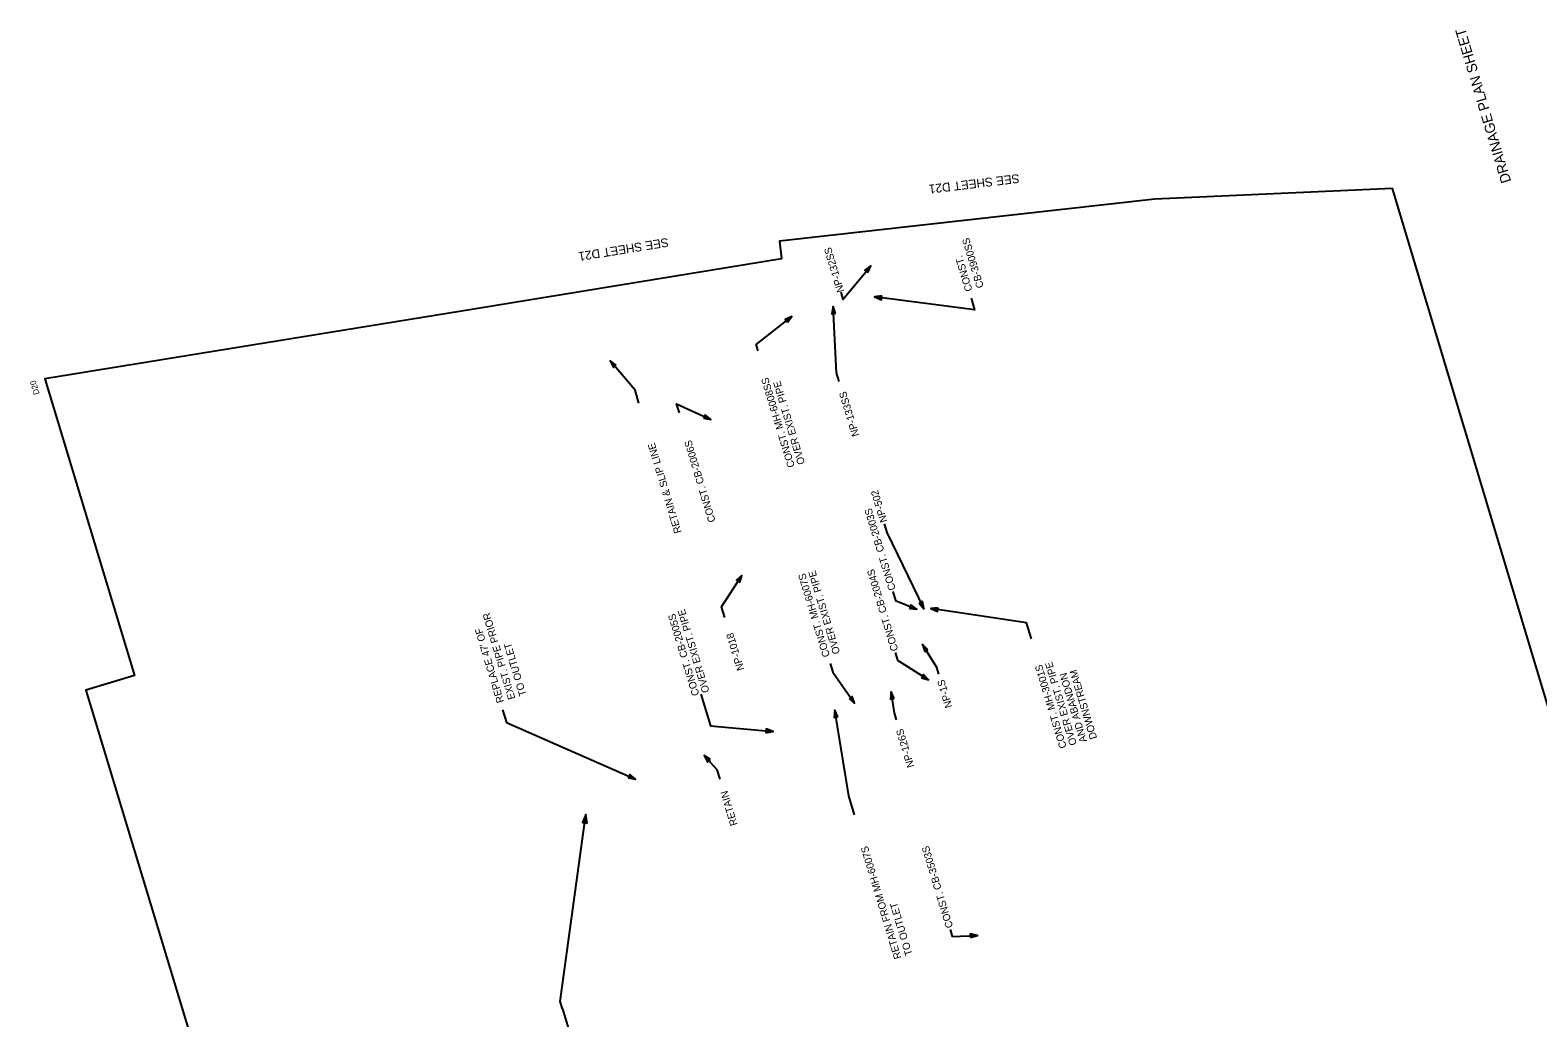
# Model space of a CAD drawing. Extents: x 1612099 to 1613927, y 1087002 to 1088782.
# Drawn here: x 1612099 to 1613125, y 1088109 to 1088782 of the extents above; entities that cross this region are included whole.
import ezdxf

# ---------------------------------------------------------------- set-up
doc = ezdxf.new("R2010")
doc.units = 0
for name, color, linetype in [('BR_CONCRETE', 7, 'Continuous'), ('RD_EX_Road', 7, 'Continuous'), ('RD_HC_CL', 7, 'Continuous'), ('RD_HY_Area_XP-Post sub TXT', 7, 'Continuous'), ('RD_HY_Misc', 7, 'Continuous')]:
    doc.layers.add(name, color=color, linetype=linetype)

msp = doc.modelspace()

# ---------------------------------------------------------------- linework, layer by layer
at = {"layer": 'BR_CONCRETE'}
msp.add_line((1612461.5, 1088115.6), (1612522, 1087914.2), dxfattribs=at)
for points in [[(1612650.9, 1088603.3), (1612652.4, 1088598.3), (1612671.3, 1088621.2)], [(1612649.9, 1088542.4), (1612648.1, 1088548.3), (1612645.7, 1088593.5)], [(1612739.6, 1088599.1), (1612742, 1088591.2), (1612673.9, 1088600)], [(1612594.6, 1088563.4), (1612593.3, 1088567.6), (1612617.7, 1088586.8)], [(1612513.5, 1088527.8), (1612510.9, 1088536.5), (1612494, 1088556.5)], [(1612541.1, 1088521.1), (1612539.2, 1088527.2), (1612562.4, 1088516.7)], [(1612680.4, 1088445.7), (1612682.2, 1088439.8), (1612707.4, 1088387.9)], [(1612572, 1088382), (1612569.8, 1088389.2), (1612583.6, 1088410.5)], [(1612686.3, 1088399.5), (1612688.1, 1088393.4), (1612702.6, 1088387.5)], [(1612780.7, 1088367.4), (1612777.4, 1088378.3), (1612712.1, 1088388)], [(1612688, 1088358.1), (1612689.6, 1088352.9), (1612710.5, 1088339.4)], [(1612717.6, 1088343.4), (1612716.2, 1088347.8), (1612706.5, 1088363.5)], [(1612643.7, 1088350.6), (1612645.4, 1088344.8), (1612660.3, 1088323.5)], [(1612555.7, 1088329.7), (1612562.2, 1088308.1), (1612604.8, 1088304.4)], [(1612688.8, 1088312.3), (1612687.4, 1088317.1), (1612685.3, 1088331.4)], [(1612420.8, 1088319.1), (1612423.4, 1088310.4), (1612511.2, 1088271.9)], [(1612660.3, 1088247.7), (1612656.4, 1088260.5), (1612646.8, 1088318.8)], [(1612568.8, 1088271.8), (1612566.8, 1088278.3), (1612557.9, 1088287.9)], [(1612461.5, 1088115.6), (1612460, 1088120.5), (1612477.4, 1088247.9)], [(1612725.3, 1088169.7), (1612726.7, 1088164.9), (1612743.9, 1088165.6)]]:
    msp.add_lwpolyline(points, dxfattribs=at)
for points in [[(1612669.2, 1088616.7), (1612671.3, 1088621.2), (1612667.2, 1088618.3)], [(1612678.9, 1088600.7), (1612673.9, 1088600), (1612678.5, 1088598.1)], [(1612647.3, 1088588.7), (1612645.7, 1088593.5), (1612644.7, 1088588.6)], [(1612614.7, 1088582.8), (1612617.7, 1088586.8), (1612613.1, 1088584.8)], [(1612498.1, 1088553.7), (1612494, 1088556.5), (1612496.2, 1088552)], [(1612557.5, 1088517.5), (1612562.4, 1088516.7), (1612558.6, 1088519.8)], [(1612582.1, 1088405.7), (1612583.6, 1088410.5), (1612579.9, 1088407.2)], [(1612697.6, 1088388.1), (1612702.6, 1088387.5), (1612698.6, 1088390.5)], [(1612704.2, 1088391.7), (1612707.4, 1088387.9), (1612706.5, 1088392.8)], [(1612717.1, 1088388.5), (1612712.1, 1088388), (1612716.7, 1088386)], [(1612710.2, 1088360), (1612706.5, 1088363.5), (1612708, 1088358.7)], [(1612705.8, 1088340.9), (1612710.5, 1088339.4), (1612707.2, 1088343.1)], [(1612656.5, 1088326.7), (1612660.3, 1088323.5), (1612658.6, 1088328.2)], [(1612687.3, 1088326.8), (1612685.3, 1088331.4), (1612684.7, 1088326.4)], [(1612648.9, 1088314.2), (1612646.8, 1088318.8), (1612646.3, 1088313.8)], [(1612599.9, 1088303.5), (1612604.8, 1088304.4), (1612600.1, 1088306.1)], [(1612562.2, 1088285.3), (1612557.9, 1088287.9), (1612560.3, 1088283.5)], [(1612506.2, 1088272.7), (1612511.2, 1088271.9), (1612507.3, 1088275)], [(1612478.3, 1088241.9), (1612477.4, 1088247.9), (1612475.2, 1088242.3)], [(1612739.1, 1088164.1), (1612743.9, 1088165.6), (1612739, 1088166.7)]]:
    msp.add_lwpolyline(points, close=True, dxfattribs=at)
at = {"layer": 'RD_HY_Misc'}
msp.add_lwpolyline([(1612576.5, 1087002), (1612843.1, 1087121.9), (1613116.7, 1087245.1), (1613415.2, 1087379), (1613026.4, 1088673.8), (1612864.6, 1088666.6), (1612609.2, 1088638), (1612610.6, 1088625.9), (1612401.2, 1088591.8), (1612109.2, 1088544.3), (1612170.2, 1088342.4), (1612137.1, 1088332.4), (1612525.2, 1087049.6), (1612547, 1087056.2)], close=True, dxfattribs=at)
msp.add_lwpolyline([(1612576.5, 1087002), (1612843.1, 1087121.9), (1613116.7, 1087245.1), (1613415.2, 1087379), (1613026.4, 1088673.8), (1612864.6, 1088666.6), (1612609.2, 1088638), (1612610.6, 1088625.9), (1612401.2, 1088591.8), (1612109.2, 1088544.3), (1612170.2, 1088342.4), (1612137.1, 1088332.4), (1612525.2, 1087049.6), (1612547, 1087056.2)], close=True, dxfattribs=at)
msp.add_lwpolyline([(1612576.5, 1087002), (1612843.1, 1087121.9), (1613116.7, 1087245.1), (1613415.2, 1087379), (1613026.4, 1088673.8), (1612864.6, 1088666.6), (1612609.2, 1088638), (1612610.6, 1088625.9), (1612401.2, 1088591.8), (1612109.2, 1088544.3), (1612170.2, 1088342.4), (1612137.1, 1088332.4), (1612525.2, 1087049.6), (1612547, 1087056.2)], close=True, dxfattribs=at)
msp.add_lwpolyline([(1612576.5, 1087002), (1612843.1, 1087121.9), (1613116.7, 1087245.1), (1613415.2, 1087379), (1613026.4, 1088673.8), (1612864.6, 1088666.6), (1612609.2, 1088638), (1612610.6, 1088625.9), (1612401.2, 1088591.8), (1612109.2, 1088544.3), (1612170.2, 1088342.4), (1612137.1, 1088332.4), (1612525.2, 1087049.6), (1612547, 1087056.2)], close=True, dxfattribs=at)
msp.add_lwpolyline([(1612576.5, 1087002), (1612843.1, 1087121.9), (1613116.7, 1087245.1), (1613415.2, 1087379), (1613026.4, 1088673.8), (1612864.6, 1088666.6), (1612609.2, 1088638), (1612610.6, 1088625.9), (1612401.2, 1088591.8), (1612109.2, 1088544.3), (1612170.2, 1088342.4), (1612137.1, 1088332.4), (1612525.2, 1087049.6), (1612547, 1087056.2)], close=True, dxfattribs=at)
msp.add_lwpolyline([(1612576.5, 1087002), (1612843.1, 1087121.9), (1613116.7, 1087245.1), (1613415.2, 1087379), (1613026.4, 1088673.8), (1612864.6, 1088666.6), (1612609.2, 1088638), (1612610.6, 1088625.9), (1612401.2, 1088591.8), (1612109.2, 1088544.3), (1612170.2, 1088342.4), (1612137.1, 1088332.4), (1612525.2, 1087049.6), (1612547, 1087056.2)], close=True, dxfattribs=at)
msp.add_lwpolyline([(1612576.5, 1087002), (1612843.1, 1087121.9), (1613116.7, 1087245.1), (1613415.2, 1087379), (1613026.4, 1088673.8), (1612864.6, 1088666.6), (1612609.2, 1088638), (1612610.6, 1088625.9), (1612401.2, 1088591.8), (1612109.2, 1088544.3), (1612170.2, 1088342.4), (1612137.1, 1088332.4), (1612525.2, 1087049.6), (1612547, 1087056.2)], close=True, dxfattribs=at)
msp.add_lwpolyline([(1612576.5, 1087002), (1612843.1, 1087121.9), (1613116.7, 1087245.1), (1613415.2, 1087379), (1613026.4, 1088673.8), (1612864.6, 1088666.6), (1612609.2, 1088638), (1612610.6, 1088625.9), (1612401.2, 1088591.8), (1612109.2, 1088544.3), (1612170.2, 1088342.4), (1612137.1, 1088332.4), (1612525.2, 1087049.6), (1612547, 1087056.2)], close=True, dxfattribs=at)
msp.add_lwpolyline([(1612576.5, 1087002), (1612843.1, 1087121.9), (1613116.7, 1087245.1), (1613415.2, 1087379), (1613026.4, 1088673.8), (1612864.6, 1088666.6), (1612609.2, 1088638), (1612610.6, 1088625.9), (1612401.2, 1088591.8), (1612109.2, 1088544.3), (1612170.2, 1088342.4), (1612137.1, 1088332.4), (1612525.2, 1087049.6), (1612547, 1087056.2)], close=True, dxfattribs=at)

# ---------------------------------------------------------------- texts
at = {"layer": 'BR_CONCRETE'}
for s, p in [('NP-132SS', (1612653.3, 1088604)), ('CB-3900SS', (1612748.3, 1088606.9)), ('CONST.', (1612740.6, 1088604.6)), ('CONST. MH-6008SS', (1612619.7, 1088484.8)), ('OVER EXIST. PIPE', (1612626.6, 1088486.8)), ('NP-133SS', (1612663.5, 1088505.9)), ('RETAIN & SLIP LINE', (1612542.6, 1088440)), ('CONST. CB-2006S', (1612565.8, 1088447.5)), ('NP-502', (1612682.6, 1088447.4)), ('CONST. CB-2003S', (1612688.4, 1088401.2)), ('CONST. MH-6007S', (1612643.6, 1088355.8)), ('OVER EXIST. PIPE', (1612650.5, 1088357.8)), ('CONST. CB-2004S', (1612690.1, 1088359.8)), ('EXIST. PIPE PRIOR ', (1612429.5, 1088326.9)), ('OVER EXIST. PIPE', (1612561.6, 1088331.5)), ('CONST. CB-2005S', (1612554.7, 1088329.4)), ("REPLACE 47' OF", (1612421.8, 1088324.6)), ('NP-1018', (1612585.2, 1088346.6)), ('TO OUTLET', (1612437.1, 1088329.2)), ('CONST. MH-3001S', (1612804.7, 1088293.7)), ('OVER EXIST. PIPE', (1612811.6, 1088295.7)), ('AND ABANDON', (1612818.5, 1088297.8)), ('DOWNSTREAM', (1612825.4, 1088299.9)), ('NP-1S', (1612726.9, 1088321.2)), ('NP-126S', (1612701, 1088280.6)), ('RETAIN', (1612580.7, 1088241)), ('RETAIN FROM MH-6007S', (1612692.2, 1088150.3)), ('CONST. CB-3503S', (1612727.4, 1088171.4)), ('TO OUTLET', (1612699.8, 1088152.6))]:
    msp.add_text(s, height=5, rotation=106.7335, dxfattribs=at).set_placement(p)
at = {"layer": 'RD_EX_Road'}
msp.add_text('DRAINAGE PLAN SHEET', height=6.983, rotation=106.7335, dxfattribs=at).set_placement((1613107.2, 1088678.7))
at = {"layer": 'RD_HC_CL'}
msp.add_text('D20', height=4, rotation=106.7335, dxfattribs=at).set_placement((1612105.7, 1088534.2))
at = {"layer": 'RD_HY_Area_XP-Post sub TXT'}
for rotation, p in [(186.8703, (1612772.1, 1088683.7)), (189.2335, (1612533.2, 1088640.3))]:
    msp.add_text('SEE SHEET D21', height=6, rotation=rotation, dxfattribs=at).set_placement(p)

doc.saveas('drawing.dxf')
